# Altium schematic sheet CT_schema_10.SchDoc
size 385 x 278 mm
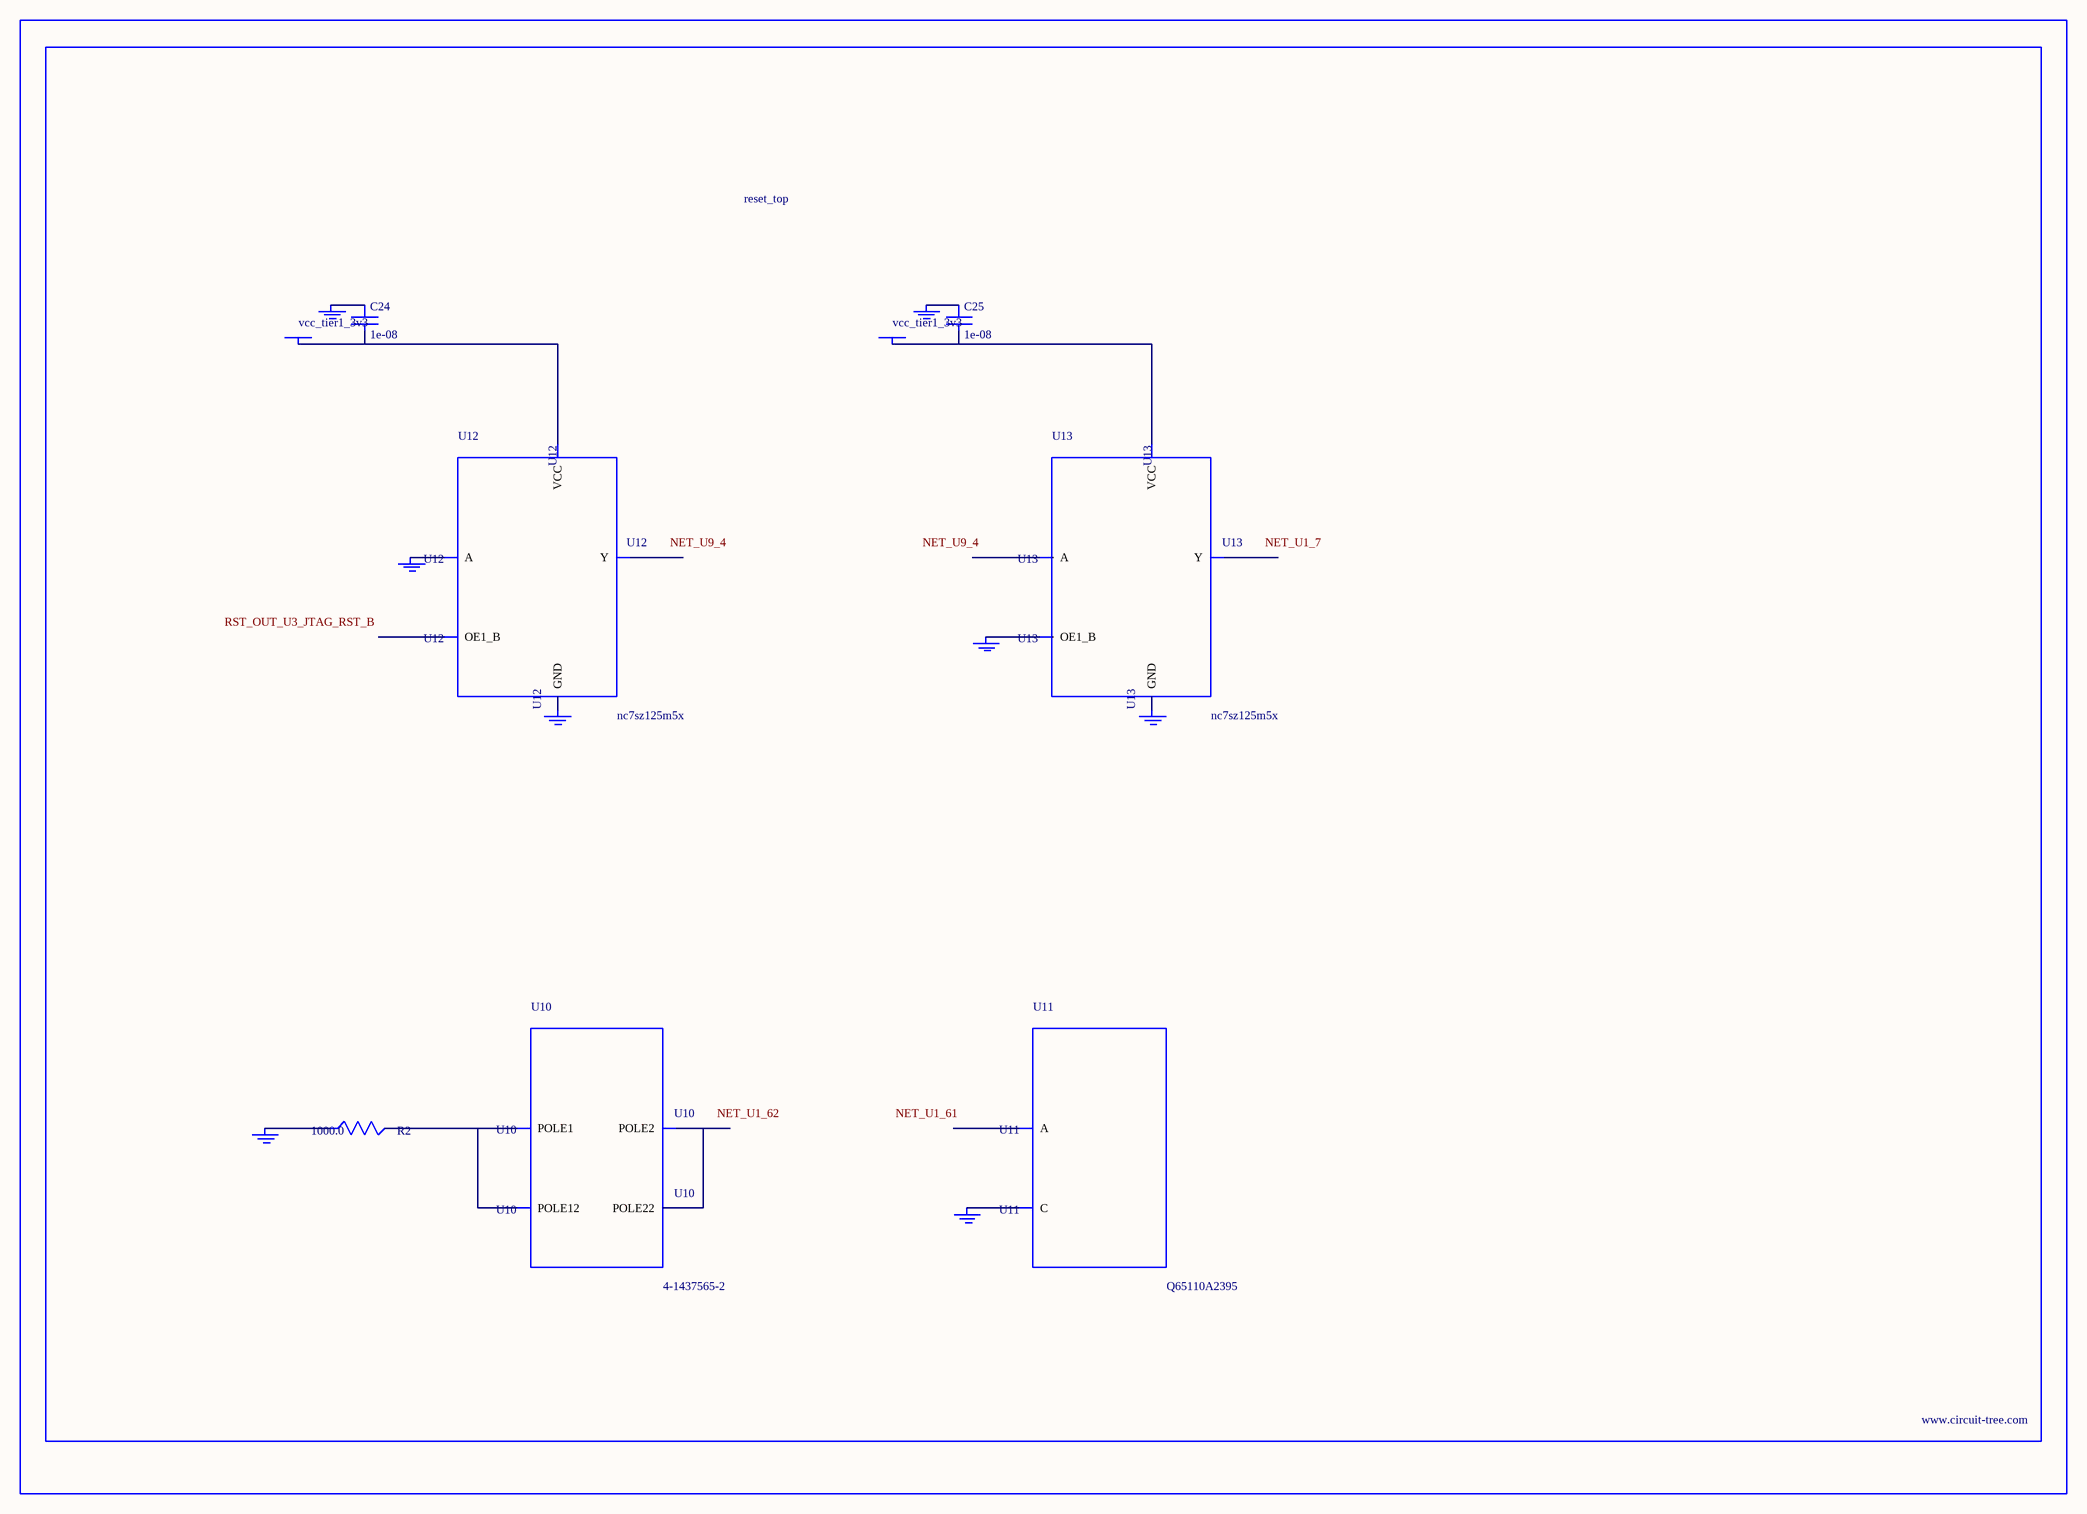
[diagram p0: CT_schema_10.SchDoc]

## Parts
BORDER9  (no value)
C24  1e-08  [C0402]
C25  1e-08  [C0402]
GND_INSTANCE_9_0  (no value)
GND_INSTANCE_9_1  (no value)
GND_INSTANCE_9_2  (no value)
GND_INSTANCE_9_3  (no value)
GND_INSTANCE_9_4  (no value)
GND_INSTANCE_9_5  (no value)
GND_INSTANCE_9_6  (no value)
GND_INSTANCE_9_7  (no value)
POWER_INSTANCE_9_0  vcc_tier1_3v3
POWER_INSTANCE_9_1  vcc_tier1_3v3
R2  1000.0  [R0603]
U10  4-1437565-2  [SW_4-1437565-2]
U11  Q65110A2395  [LGM67K-G1J2-24-Z]
U12  nc7sz125m5x  [NC7SZ125M5X]
U13  nc7sz125m5x  [NC7SZ125M5X]

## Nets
NetC24_1: C24.1 GND_INSTANCE_9_2.0(GND)
NetC24_2: C24.2 POWER_INSTANCE_9_0.0(PWR) U12.5(VCC)
NetC25_1: C25.1 GND_INSTANCE_9_5.0(GND)
NetC25_2: C25.2 POWER_INSTANCE_9_1.0(PWR) U13.5(VCC)
NetGND_INSTANCE_9_0_0: GND_INSTANCE_9_0.0(GND) R2.1
NetGND_INSTANCE_9_1_0: GND_INSTANCE_9_1.0(GND) U11.C
NetGND_INSTANCE_9_3_0: GND_INSTANCE_9_3.0(GND) U12.2(A)
NetGND_INSTANCE_9_4_0: GND_INSTANCE_9_4.0(GND) U12.3(GND)
NetGND_INSTANCE_9_6_0: GND_INSTANCE_9_6.0(GND) U13.1(OE1_B)
NetGND_INSTANCE_9_7_0: GND_INSTANCE_9_7.0(GND) U13.3(GND)
NetR2_2: R2.2 U10.1(POLE1) U10.2(POLE12)
NetU10_3: U10.3(POLE2) U10.4(POLE22)

Not connected (* = marked no-connect by the designer): U11 A; U12 1(OE1_B) 4(Y); U13 2(A) 4(Y)

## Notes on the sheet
- Labels drawn without touching a wire or pin: NET_U1_7, NET_U1_61, NET_U1_62, NET_U9_4, RST_OUT_U3_JTAG_RST_B

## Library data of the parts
BORDER9 = BORDER_PAGE9
C24 C25 = C0402C103K3RAC
GND_INSTANCE_9_0-GND_INSTANCE_9_7 = GND
POWER_INSTANCE_9_0 POWER_INSTANCE_9_1 = PWR
R2 = RC0603JR-071KL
